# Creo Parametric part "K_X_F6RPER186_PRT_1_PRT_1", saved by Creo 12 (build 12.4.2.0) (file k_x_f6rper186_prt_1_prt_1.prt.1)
Units: Custom; MM, KILOGRAM, SECS

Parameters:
  PTC_WM_ITERATION = "0"
  PTC_WM_VERSION = "-.0"
  PTC_WM_LIFECYCLE_STATE = "In Work"
  PTC_WM_LIFECYCLE = "MO_CADDocument"
  PTC_WM_CREATED_BY = "Maximilian Roepper (Z0017RMS: MO)"
  PTC_WM_CREATED_ON = "18-Sep-26 11:36:42 AM"
  PTC_WM_MODIFIED_BY = "Maximilian Roepper (Z0017RMS: MO)"
  PTC_WM_MODIFIED_ON = "18-Sep-26 11:36:46 AM"
  PDMLINKNUMBER = "PDM000071455305"
  PTC_WM_NAME = "k_x_f6rper186_prt_1_prt_1.prt"
  PTC_WM_NUMBER = "PDM000071455305"

Other parameters: WEIGHT, WEIGHT_FACTOR, WEIGHT_ADD, _MASS_TEMP, _DIFF_TEMP, MC_ERRORS, SUPPLIER

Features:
  1. coordinate system
  2. datum plane "PRT_YZ"
  3. datum plane "PRT_XY"
  4. datum plane "PRT_XZ"
  5. coordinate system
  6. datum axis
  7. datum axis
  8. datum axis
  9. coordinate system
  10. imported feature
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
Other named items: PRT, SIEMENS_MO, DRW_VIEW_ORG, PRT_X, PRT_Y, PRT_Z, CS0, ROUGH_GROB

Layers: 00_STD_CSYS-KSYS, 01_STD_PLANES-EBENEN, 02_STD_AXES-ACHSEN, 03_STD_CSYS-KSYS, 24_IMPORT_FEAT-IMPORT_KE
